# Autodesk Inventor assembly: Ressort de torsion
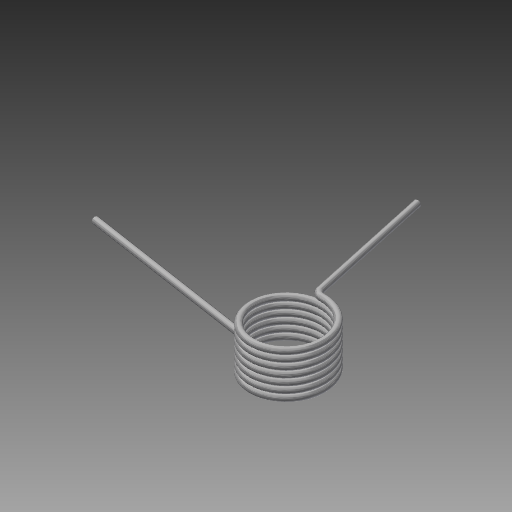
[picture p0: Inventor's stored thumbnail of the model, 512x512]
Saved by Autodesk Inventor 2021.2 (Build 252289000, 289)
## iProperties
ClientObjectVersion: 1
Created: 2018-06
Part Number: Ressort de torsion
Document SubType Name: Assembly
Designer: Fabian Perrée
Author: Fabian Perrée
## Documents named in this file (2)
- C:\Users\Fabian\Google Drive\04_CAO\01_Inventor\01_Fichiers_exercice_Inventor\01_Definitif\Capteur\Ens_levier\Design Accelerator\Ressort de torsion1.iam
- C:\Users\Fabian\Google Drive\04_CAO\01_Inventor\01_Fichiers_exercice_Inventor\01_Definitif\Capteur\Ens_levier\Design Accelerator\Ressort de torsion1.ipt
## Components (1 placed, 1 different names)
1. Ressort de torsion:1
